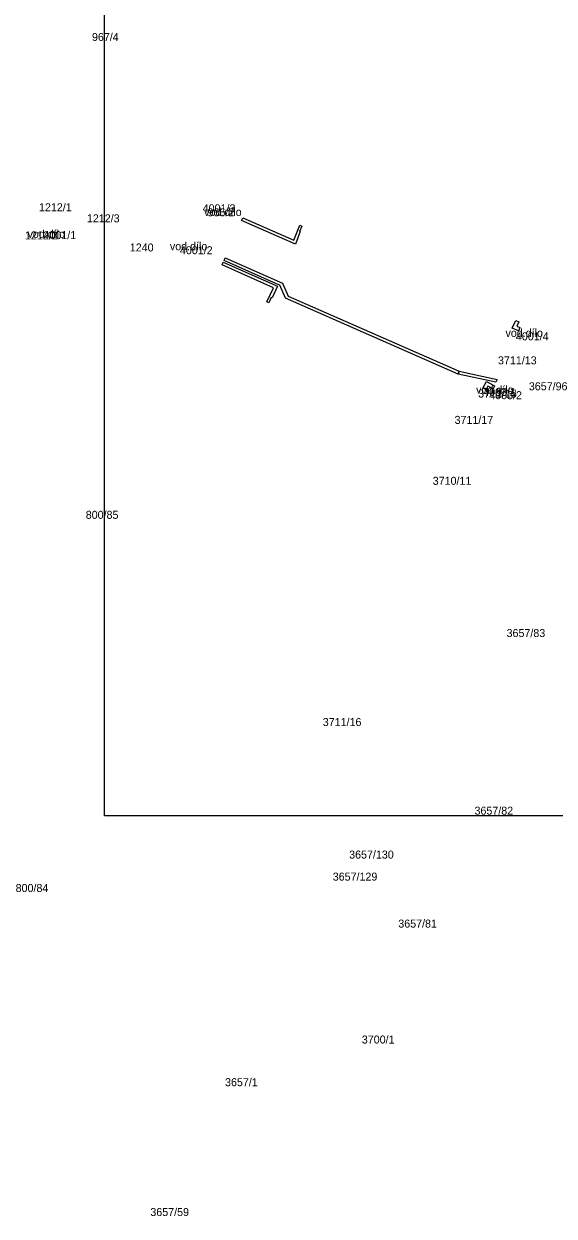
# Model space of a CAD drawing. Extents: x -755751 to -744370, y -967072 to -958435.
# Drawn here: x -747933.6 to -747820.8, y -965659.3 to -965406 of the extents above; entities that cross this region are included whole.
import ezdxf

# ---------------------------------------------------------------- set-up
doc = ezdxf.new("R2010")
doc.units = 0
for name, color, linetype in [('Vrstva 13', 7, 'Continuous'), ('Vrstva 50', 7, 'Continuous'), ('Vrstva 63', 7, 'Continuous')]:
    doc.layers.add(name, color=color, linetype=linetype)

msp = doc.modelspace()

# ---------------------------------------------------------------- linework, layer by layer
at = {"layer": 'Vrstva 13'}
for points in [[(-747887.02, -965447.23), (-747876.17, -965451.98), (-747874.93, -965448.81), (-747874.48, -965449.03), (-747874.94, -965450.11), (-747874.8, -965450.15), (-747875.8, -965452.83), (-747887.28, -965447.82)], [(-747880.81, -965464.2), (-747880.98, -965464.12), (-747881.47, -965465.27), (-747881.91, -965465.04), (-747880.48, -965462.08), (-747891.43, -965457.23), (-747891.18, -965456.66), (-747879.63, -965461.78)], [(-747841.26, -965480.42), (-747877.96, -965464.32), (-747879.14, -965461.56), (-747879.87, -965461.24), (-747891.02, -965456.3), (-747890.76, -965455.71), (-747878.6, -965461.09), (-747877.39, -965463.86), (-747841, -965479.82)], [(-747828.22, -965470.74), (-747828.43, -965471.23), (-747829.77, -965470.65), (-747829.01, -965469.03), (-747828.31, -965469.35), (-747828.74, -965470.27), (-747828.13, -965470.53)], [(-747833.21, -965482.15), (-747841.26, -965480.42), (-747841, -965479.82), (-747832.95, -965481.56)], [(-747833.83, -965483.57), (-747834.93, -965482.99), (-747835.29, -965483.71), (-747835.99, -965483.42), (-747835.25, -965482), (-747833.53, -965482.89)]]:
    msp.add_lwpolyline(points, close=True, dxfattribs=at)
at = {"layer": 'Vrstva 63'}
msp.add_lwpolyline([(-747916.439, -965165.632), (-747328.029, -965165.632), (-747328.029, -965574.289), (-747916.439, -965574.289)], close=True, dxfattribs=at)

# ---------------------------------------------------------------- texts
at = {"layer": 'Vrstva 50'}
for s, p in [('967/4', (-747919.095, -965409.65)), ('1212/1', (-747930.359, -965445.83)), ('4001/3', (-747895.557, -965446.05)), ('1212/3', (-747920.173, -965448.18)), ('vod.dílo', (-747895.238, -965446.82)), ('966/2', (-747894.527, -965446.91)), ('1212/2', (-747933.333, -965451.82)), ('vod.dílo', (-747932.788, -965451.5)), ('4001/1', (-747929.403, -965451.75)), ('1240', (-747911.051, -965454.37)), ('vod.dílo', (-747902.528, -965454.11)), ('4001/2', (-747900.397, -965454.96)), ('vod.dílo', (-747831.178, -965472.53)), ('4001/4', (-747828.967, -965473.25)), ('3711/13', (-747832.774, -965478.36)), ('3657/96', (-747826.217, -965483.87)), ('vod.dílo', (-747837.418, -965484.61)), ('3711/15', (-747836.994, -965485.41)), ('4003/1', (-747835.903, -965485.06)), ('4003/2', (-747834.637, -965485.76)), ('3711/17', (-747842.004, -965491.01)), ('3710/11', (-747846.653, -965503.95)), ('800/85', (-747920.421, -965511.18)), ('3657/83', (-747830.947, -965536.3)), ('3711/16', (-747870.024, -965555.21)), ('3657/82', (-747837.767, -965574.04)), ('3657/130', (-747864.418, -965583.37)), ('3657/129', (-747867.902, -965588.05)), ('800/84', (-747935.321, -965590.47)), ('3657/81', (-747853.974, -965598.03)), ('3700/1', (-747861.723, -965622.67)), ('3657/1', (-747890.805, -965631.73)), ('3657/59', (-747906.687, -965659.32))]:
    msp.add_text(s, height=1.7, dxfattribs=at).set_placement(p)

doc.saveas('drawing.dxf')
